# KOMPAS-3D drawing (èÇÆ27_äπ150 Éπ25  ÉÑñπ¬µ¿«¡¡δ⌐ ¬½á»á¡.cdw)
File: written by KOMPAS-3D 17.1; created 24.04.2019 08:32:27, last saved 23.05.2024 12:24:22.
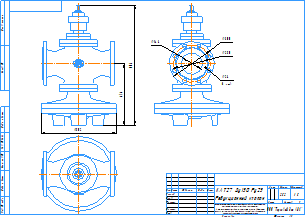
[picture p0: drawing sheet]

Sheet 1: A3, landscape

Title block, sheet 1: name: КАТ27 Ду150 Ру25 / Редукционный клапан; material: Сталь 20  ГОСТ 1050-88; mass: 252; sheets: 1; sheet format: A3; stored path: D:\Документы\Компас\Поставщики\Armstrong\Редукционный клапан GP-2000\KOMPAS 2D\Анн\GP-2000 _ Ду100 Ру25  Редукционный клапан.cdw

Views: Вид 1
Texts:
  adm
  Рама для чертежей
  Лит-Масса-Масштаб
  Материал-Предприятие
  Масштаб
  Изм.
  Лист
  № докум.
  Подп.
  Дата
  Лит.
  Разраб.
  Пров.
  Т.контр.
  Листов
  Внимание! Данный продукт является объектом авторского права ООО «Торговый Дом АДЛ».
  Запрещается изменение, копирование, распространение
  (в том числе путем копирования на другие сайты и ресурсы в Интернете)
  или любое иное использование информации и объектов без предварительного
  согласия правообладателя (ООО «Торговый Дом АДЛ»).
  Н.контр.
  Утв.
  ООО "Торговый дом АДЛ"
  Изменение
  Номер документа
  Подпись
  Обозначение документа
  Наименование изделия
  Масса изделия по ГОСТ 2.109-73
  Порядковый номер листа
  Общее количество листов в документе
  Характер работы, выполненной лицом, подписавшим документ
  Наименование или индекс предприятия, выпускающего документ
  Инв. № подл.
  Подп. и дата
  Взам. инв. №
  Инв. № дубл.
  Инвентарный номер подлинника по ГОСТ 2.501-68
  Подпись принявшего подлинник в отдел технической документации
  Инвентарный номер подлинника, взамен которого выпущен данный подлинник
  Инвентарный номер дубликата по ГОСТ 2.502-68
  Подпись принявшего дубликат в отдел технической документации
  Справ. №
  Перв. примен.
  Обозначение документа, взамен или на основании которого выпущен данный документ
  Обозначение документа, в котором впервые записан данный документ
  Подпись лица, копировавшего чертеж
  Обозначение формата листа
  !Рама для чертежа
Dimensions and other numbers on the sheet: 502; 414; 806; 300; 250; 26; 8 отв.; 146; 1:5; 1; 252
